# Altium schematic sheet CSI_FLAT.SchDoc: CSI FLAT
size A4; Author: Silvio Navaretti; CompanyName: Arduino SRL; DrawnBy: Silvio Navaretti; Engineer: Silvio Navaretti; Organization: Arduino SRL; DocumentNumber: ASX00083; SheetNumber: 6; SheetTotal: 11; RevAuthor: Silvio Navaretti
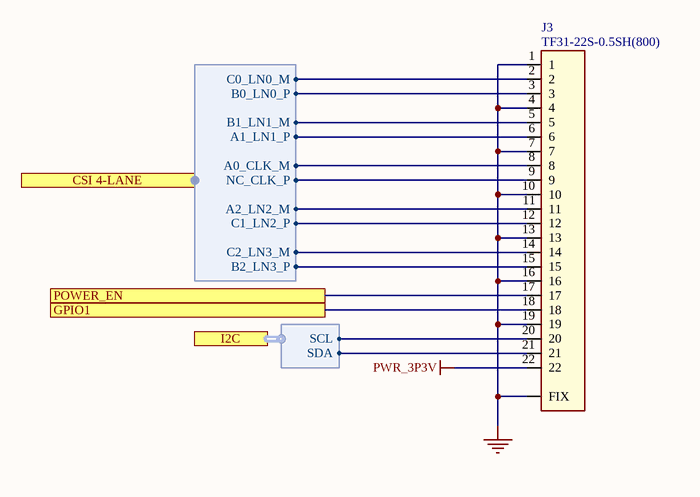
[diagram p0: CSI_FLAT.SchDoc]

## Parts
J3  TF31-22S-0.5SH(800)  [TF31-22S-0.5SH(800)]

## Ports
CSI 4-LANE (harness IMOLA_CSI), GPIO1, I2C (harness I2C), POWER_EN

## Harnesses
I2C: SDA, SCL
IMOLA_CSI: C2_LN3_M, A2_LN2_M, C1_LN2_P, C0_LN0_M, B0_LN0_P, A0_CLK_M, NC_CLK_P, B1_LN1_M, A1_LN1_P, B2_LN3_P

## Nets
GND: J3.1 J3.4 J3.7 J3.10 J3.13 J3.16 J3.19 J3.FIX
PWR_3P3V: J3.22
GPIO1: J3.18 ; port GPIO1
POWER_EN: J3.17 ; port POWER_EN
NetJ3_2: J3.2 ; port CSI 4-LANE.C0_LN0_M
NetJ3_3: J3.3 ; port CSI 4-LANE.B0_LN0_P
NetJ3_5: J3.5 ; port CSI 4-LANE.B1_LN1_M
NetJ3_6: J3.6 ; port CSI 4-LANE.A1_LN1_P
NetJ3_8: J3.8 ; port CSI 4-LANE.A0_CLK_M
NetJ3_9: J3.9 ; port CSI 4-LANE.NC_CLK_P
NetJ3_11: J3.11 ; port CSI 4-LANE.A2_LN2_M
NetJ3_12: J3.12 ; port CSI 4-LANE.C1_LN2_P
NetJ3_14: J3.14 ; port CSI 4-LANE.C2_LN3_M
NetJ3_15: J3.15 ; port CSI 4-LANE.B2_LN3_P
NetJ3_20: J3.20 ; port I2C.SCL
NetJ3_21: J3.21 ; port I2C.SDA

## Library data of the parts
J3 = J0553-A.2: CONN FFC/FPC Connector, 22 Contact(s), 1 Row(s), BOTTOM CONTACT, Female, Right Angle, 0.5mm Pitch; Manufacturer: Hirose; Code Arduino: J0553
